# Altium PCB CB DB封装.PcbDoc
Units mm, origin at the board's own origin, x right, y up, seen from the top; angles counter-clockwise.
Board outline 43.2 x 10 mm, 2 copper layers (Top Layer, Bottom Layer); 0 components, 14 nets, 5 pads, 0 vias.
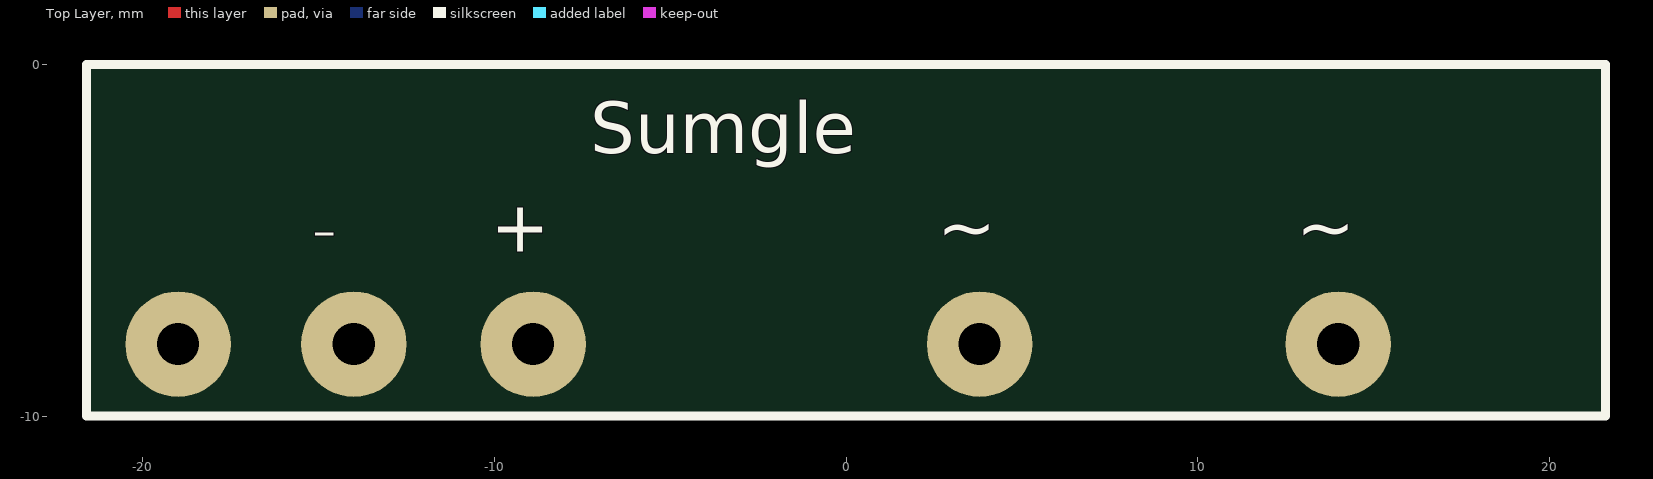
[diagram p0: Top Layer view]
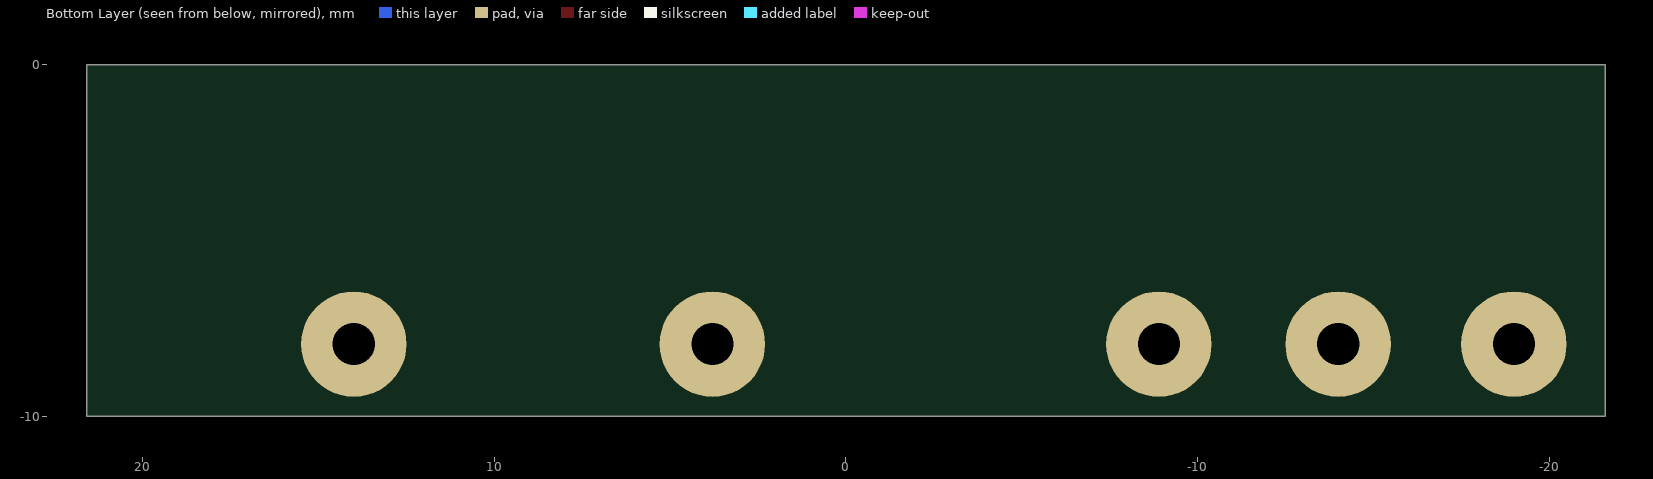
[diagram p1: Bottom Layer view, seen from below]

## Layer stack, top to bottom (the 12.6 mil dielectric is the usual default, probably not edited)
Top Layer: signal copper 0.0356
Dielectric: dielectric 0.32, FR-4, Dk 4.8
Bottom Layer: signal copper 0.0356

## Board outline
-21.6,-10 -21.6,0 21.6,0 21.6,-10

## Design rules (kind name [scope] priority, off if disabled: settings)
Clearance [All] p1: gap=0.254
PolygonConnect [All] p1: connectstyle=Relief reliefconductorwidth=0.254 reliefentries=4 polygonreliefangle="90 Angle"
RoutingVias [All] p1: holewidth=0.711 width=1.27 viastyle="Through Hole" minholewidth=0.711 minwidth=1.27 maxholewidth=0.711 maxwidth=1.27
SilkscreenOverComponentPads [All] p1: minsilkscreentomaskgap=0.254
SolderMaskExpansion [All] p1: expansion=0.102
Width [All] p1: maxlimit=3 minlimit=0.254 preferedwidth=0.254 minimp=50.000000 maximp=50.000000 favimp=50.000000
27 further rules are at their usual default settings.

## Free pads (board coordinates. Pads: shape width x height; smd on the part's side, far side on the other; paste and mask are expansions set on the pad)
  round 3 hole 1.2: 1(14,-7.951) 2(3.8,-7.951) 3(-8.9,-7.951) 4(-14,-7.951) 5(-19,-7.951)

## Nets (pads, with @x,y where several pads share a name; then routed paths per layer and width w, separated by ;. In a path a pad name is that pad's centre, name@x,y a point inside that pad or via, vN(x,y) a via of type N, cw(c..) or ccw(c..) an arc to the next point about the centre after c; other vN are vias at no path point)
GND: 
NetC3_2: 
NetC5_1: 
NetCFF_2: 
NetD1_2: 
NetL1_1: 
NetL2_2: 
NetMC2_10: 
V: 
VAUX: 
VAUX2: 
VCELL: 
VOUT: 
VOUT2: 

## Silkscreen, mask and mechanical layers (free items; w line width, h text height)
Top Overlay:
  the board outline again, w0.254
  text "Sumgle" at -7.276,-3 h2.5
  text "-" at -15.199,-5.8 h2.5
  text "+" at -10.099,-5.807 h2.5
  text "~" at 2.602,-5.8 h2.5
  text "~" at 12.801,-5.8 h2.5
